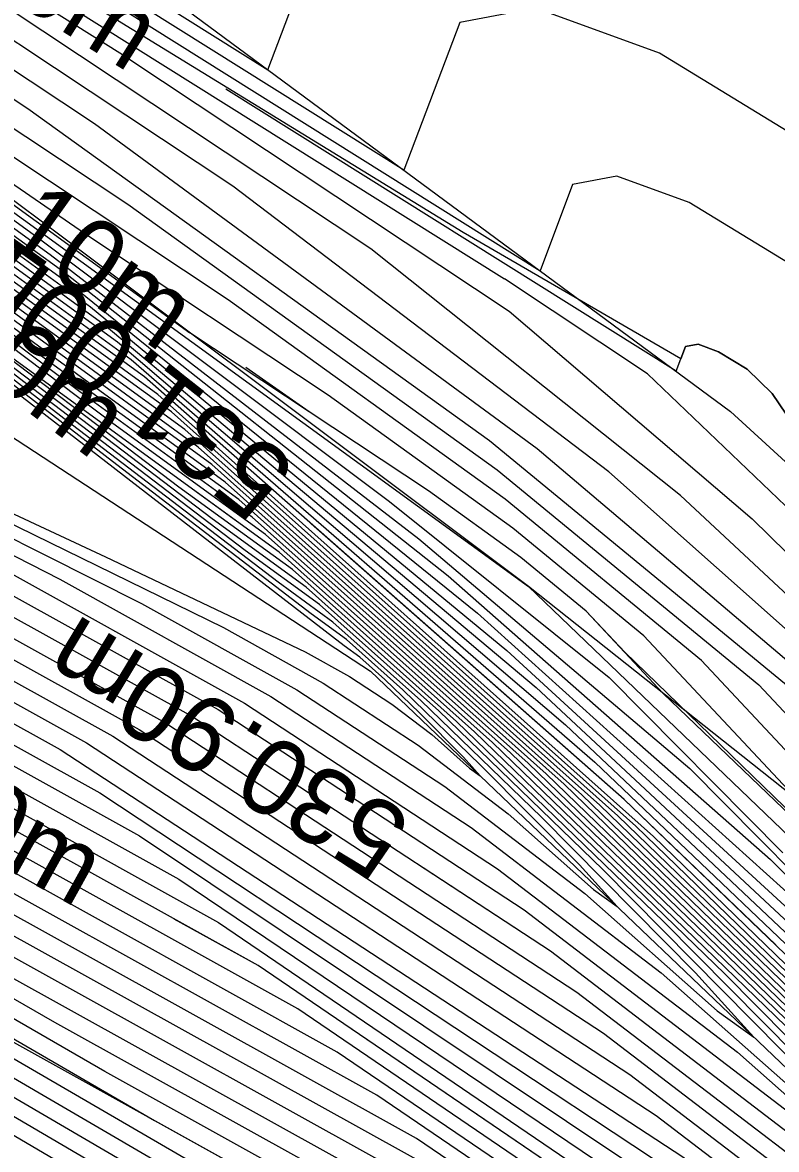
# Model space of a CAD drawing. Extents: x -866683 to -866410, y -1041951 to -1040252.
# Drawn here: x -866440.22 to -866437.24, y -1041918.091 to -1041913.64 of the extents above; entities that cross this region are included whole.
import ezdxf

# ---------------------------------------------------------------- set-up
doc = ezdxf.new("R2010")
doc.units = 0
for name, color, linetype in [('BODY', 7, 'Continuous'), ('BODY_2016', 7, 'Continuous'), ('BREAKLINE', 7, 'Continuous'), ('V-HL', 7, 'Continuous'), ('V-VEDL', 7, 'Continuous'), ('V_po_cm', 7, 'Continuous')]:
    doc.layers.add(name, color=color, linetype=linetype)

msp = doc.modelspace()

# ---------------------------------------------------------------- linework, layer by layer
at = {"layer": 'BREAKLINE'}
for points in [[(-866451.679, -1041950.508), (-866455.618, -1041922.473), (-866456.719, -1041912.396), (-866455.207, -1041909.853), (-866453.752, -1041908.342), (-866450, -1041907.538), (-866447.7, -1041908.076), (-866445.165, -1041909.459), (-866437.422, -1041915.176), (-866426.565, -1041925.108), (-866438.22, -1041915.868), (-866445.312, -1041910.554), (-866447.7, -1041908.076)], [(-866445.626, -1041911.77), (-866438.844, -1041916.202), (-866428.169, -1041926.387)]]:
    msp.add_lwpolyline(points, dxfattribs=at)
at = {"layer": 'V-HL'}
for points in [[(-866437.2433, -1041917.2832), (-866437.8418, -1041916.7086), (-866439.7378, -1041915.04), (-866442.338, -1041913.151)], [(-866436.874, -1041919.0079), (-866439.2887, -1041917.3651), (-866441.9813, -1041915.8713)]]:
    msp.add_lwpolyline(points, dxfattribs=at)
at = {"layer": 'V-VEDL'}
for points in [[(-866444.4177, -1041911.3349), (-866439.5581, -1041914.8654)], [(-866437.1745, -1041915.2278), (-866437.2577, -1041915.1049), (-866437.3558, -1041915.009), (-866437.4688, -1041914.9401), (-866437.5503, -1041914.9104), (-866437.6002, -1041914.9199), (-866437.6187, -1041914.9686), (-866438.479, -1041914.4699), (-866440.1812, -1041913.4239)], [(-866442.5339, -1041914.7256), (-866439.5509, -1041916.3805), (-866438.1333, -1041917.3074), (-866436.7895, -1041918.3338), (-866435.5196, -1041919.4596), (-866435.1652, -1041919.7133), (-866435.7263, -1041919.0949), (-866437.2029, -1041917.6045), (-866438.3627, -1041916.4834), (-866439.2058, -1041915.7317), (-866440.2582, -1041914.9671)], [(-866427.6159, -1041925.946), (-866434.3305, -1041919.5086), (-866436.6195, -1041917.3087), (-866437.8401, -1041916.1275), (-866437.9924, -1041915.9651), (-866438.251, -1041915.7527), (-866438.6158, -1041915.4903), (-866439.5581, -1041914.8654)], [(-866441.6705, -1041916.8829), (-866437.7247, -1041919.072), (-866435.6089, -1041920.5114), (-866433.3503, -1041922.2956), (-866428.5474, -1041926.5536)]]:
    msp.add_lwpolyline(points, dxfattribs=at)
at = {"layer": 'V_po_cm'}
for points in [[(-866435.0469, -1041921.2152), (-866436.9427, -1041919.9254), (-866438.7106, -1041918.9447), (-866440.4558, -1041917.9193), (-866442.1783, -1041916.8494), (-866443.8783, -1041915.7348), (-866445.0517, -1041915.0023), (-866445.6985, -1041914.6519), (-866445.8188, -1041914.6836), (-866446.0099, -1041914.5257), (-866446.2718, -1041914.1783), (-866446.6045, -1041913.6413), (-866446.7592, -1041913.2564), (-866446.7361, -1041913.0236), (-866446.5351, -1041912.9428), (-866446.5915, -1041912.6551), (-866446.9053, -1041912.1604), (-866447.4766, -1041911.4587), (-866447.7506, -1041910.8145), (-866447.7273, -1041910.2278), (-866447.4067, -1041909.6986), (-866447.002, -1041909.4933), (-866446.5131, -1041909.6119), (-866445.3672, -1041910.4968)], [(-866445.9977, -1041909.8425), (-866445.4973, -1041909.9944), (-866444.6642, -1041910.4624), (-866443.2481, -1041911.3223), (-866439.2502, -1041913.8262)], [(-866438.7125, -1041914.2232), (-866443.0739, -1041911.4917), (-866444.6015, -1041910.5588), (-866445.476, -1041910.0588), (-866445.9189, -1041909.9243)], [(-866445.84, -1041910.0061), (-866445.4547, -1041910.1231), (-866444.5388, -1041910.6553), (-866442.8996, -1041911.6611), (-866438.1748, -1041914.6202)], [(-866433.8924, -1041920.7967), (-866436.2376, -1041918.4294), (-866438.0796, -1041916.6489), (-866439.4186, -1041915.455), (-866440.2543, -1041914.8478), (-866441.2908, -1041914.0728), (-866442.5279, -1041913.1298), (-866443.9657, -1041912.019), (-866445.0628, -1041911.1714), (-866445.8192, -1041910.5872), (-866446.2349, -1041910.2662), (-866446.587, -1041910.1759), (-866446.8755, -1041910.3165), (-866447.3254, -1041911.0592), (-866445.9448, -1041912.755), (-866445.4235, -1041913.3485), (-866445.0711, -1041913.6876), (-866444.8878, -1041913.7724), (-866443.9759, -1041914.2669), (-866442.3355, -1041915.1713), (-866439.9667, -1041916.4855), (-866437.7152, -1041917.9576), (-866435.581, -1041919.5877), (-866433.5641, -1041921.3758)], [(-866445.6824, -1041910.1696), (-866445.4121, -1041910.2517), (-866444.5485, -1041910.7635), (-866442.9564, -1041911.7461), (-866438.3152, -1041914.6528)], [(-866436.4789, -1041918.2232), (-866438.1504, -1041916.6075), (-866439.3654, -1041915.5242), (-866440.1238, -1041914.9732), (-866441.1322, -1041914.2174), (-866442.3908, -1041913.2567), (-866443.8994, -1041912.0912), (-866445.0409, -1041911.2093), (-866445.8152, -1041910.6111), (-866446.2225, -1041910.2966), (-866446.5675, -1041910.2082), (-866446.8502, -1041910.3459), (-866447.291, -1041911.0736), (-866445.9384, -1041912.7351), (-866445.3652, -1041913.3454), (-866444.8953, -1041913.7353), (-866444.5285, -1041913.9048), (-866443.5675, -1041914.4152), (-866442.0123, -1041915.2667), (-866439.8628, -1041916.4592), (-866437.8197, -1041917.7951), (-866435.8831, -1041919.2742)], [(-866436.7203, -1041918.0169), (-866438.2212, -1041916.5661), (-866439.3122, -1041915.5933), (-866439.9932, -1041915.0986), (-866440.9736, -1041914.362), (-866442.2536, -1041913.3836), (-866443.833, -1041912.1633), (-866445.0189, -1041911.2471), (-866445.8113, -1041910.635), (-866446.2102, -1041910.327), (-866446.5481, -1041910.2405), (-866446.8249, -1041910.3753), (-866447.2566, -1041911.088), (-866445.9319, -1041912.7151), (-866445.307, -1041913.3422), (-866444.7194, -1041913.7829), (-866444.1693, -1041914.0371), (-866443.1591, -1041914.5636), (-866441.689, -1041915.3622), (-866439.7588, -1041916.433), (-866437.9242, -1041917.6325), (-866436.1852, -1041918.9607)], [(-866439.8039, -1041913.7807), (-866443.4576, -1041911.4925), (-866444.7109, -1041910.7189), (-866445.3908, -1041910.316), (-866445.6036, -1041910.2514)], [(-866436.9616, -1041917.8107), (-866438.292, -1041916.5247), (-866439.259, -1041915.6625), (-866439.8626, -1041915.224), (-866440.8151, -1041914.5066), (-866442.1165, -1041913.5105), (-866443.7667, -1041912.2355), (-866444.997, -1041911.285), (-866445.8074, -1041910.659), (-866446.1979, -1041910.3575), (-866446.5286, -1041910.2727), (-866446.7996, -1041910.4048), (-866447.2222, -1041911.1024), (-866445.9255, -1041912.6952), (-866445.2487, -1041913.3391), (-866444.5436, -1041913.8305), (-866443.81, -1041914.1695), (-866442.7507, -1041914.7119), (-866441.3657, -1041915.4576), (-866439.6549, -1041916.4067), (-866438.0288, -1041917.4699), (-866436.4874, -1041918.6473)], [(-866436.1848, -1041918.6695), (-866437.4443, -1041917.3982), (-866438.4335, -1041916.442), (-866439.1526, -1041915.8008), (-866439.6014, -1041915.4748), (-866440.4979, -1041914.7959), (-866441.8422, -1041913.7642), (-866443.6341, -1041912.3798), (-866444.9532, -1041911.3607), (-866445.7996, -1041910.7069), (-866446.1732, -1041910.4184), (-866446.4897, -1041910.3373), (-866446.7491, -1041910.4636), (-866447.1534, -1041911.1311), (-866445.9126, -1041912.6553), (-866445.1322, -1041913.3328), (-866444.1918, -1041913.9258), (-866443.0915, -1041914.4343), (-866441.934, -1041915.0085), (-866440.7191, -1041915.6485), (-866439.4469, -1041916.3542), (-866438.2378, -1041917.1448), (-866437.0916, -1041918.0203)], [(-866436.6433, -1041918.2441), (-866437.6856, -1041917.192), (-866438.5043, -1041916.4006), (-866439.0994, -1041915.87), (-866439.4708, -1041915.6001), (-866440.3394, -1041914.9405), (-866441.705, -1041913.8911), (-866443.5677, -1041912.452), (-866444.9313, -1041911.3985), (-866445.7957, -1041910.7308), (-866446.1609, -1041910.4488), (-866446.4703, -1041910.3696), (-866446.7238, -1041910.493), (-866447.119, -1041911.1455), (-866445.9061, -1041912.6354), (-866445.0739, -1041913.3297), (-866444.016, -1041913.9735), (-866442.7323, -1041914.5666), (-866441.5256, -1041915.1568), (-866440.3958, -1041915.7439), (-866439.343, -1041916.328), (-866438.3423, -1041916.9823), (-866437.3938, -1041917.7068), (-866436.4974, -1041918.5015)], [(-866437.1018, -1041917.8186), (-866437.9269, -1041916.9857), (-866438.5751, -1041916.3592), (-866439.0462, -1041915.9392), (-866439.3402, -1041915.7255), (-866440.1808, -1041915.0851), (-866441.5679, -1041914.018), (-866443.5014, -1041912.5242), (-866444.9094, -1041911.4364), (-866445.7918, -1041910.7548), (-866446.1486, -1041910.4793), (-866446.4508, -1041910.4018), (-866446.6985, -1041910.5225), (-866447.0846, -1041911.1599), (-866445.8997, -1041912.6154), (-866445.0156, -1041913.3266), (-866443.8401, -1041914.0211), (-866442.373, -1041914.699), (-866441.1172, -1041915.3051), (-866440.0725, -1041915.8393), (-866439.239, -1041916.3017), (-866438.4468, -1041916.8197), (-866437.6959, -1041917.3933), (-866436.9862, -1041918.0224)], [(-866444.2699, -1041911.1645), (-866439.9355, -1041914.039), (-866438.1861, -1041915.322), (-866436.8545, -1041916.4507), (-866435.0268, -1041918.3995)], [(-866434.4947, -1041918.8214), (-866436.6269, -1041916.5478), (-866437.903, -1041915.415), (-866439.3891, -1041914.2862), (-866442.7812, -1041912.0365)], [(-866442.5549, -1041912.4171), (-866440.1992, -1041913.9793), (-866438.375, -1041915.2915), (-866437.0821, -1041916.3536)], [(-866444.9574, -1041913.3234), (-866443.6642, -1041914.0687), (-866442.0138, -1041914.8314), (-866440.7088, -1041915.4534), (-866439.7492, -1041915.9348), (-866439.1351, -1041916.2755), (-866438.5513, -1041916.6572), (-866437.998, -1041917.0798), (-866437.4751, -1041917.5434), (-866437.3292, -1041917.6478), (-866437.5602, -1041917.3932), (-866438.1683, -1041916.7795), (-866438.6458, -1041916.3179), (-866438.993, -1041916.0083), (-866439.2096, -1041915.8509), (-866440.0222, -1041915.2298), (-866441.4307, -1041914.1449), (-866443.4351, -1041912.5963)], [(-866444.8991, -1041913.3203), (-866443.4884, -1041914.1164), (-866441.6546, -1041914.9638), (-866440.3004, -1041915.6017), (-866439.4259, -1041916.0302), (-866439.0311, -1041916.2492), (-866438.6559, -1041916.4946), (-866438.3002, -1041916.7663), (-866437.964, -1041917.0643), (-866437.8702, -1041917.1315), (-866438.0187, -1041916.9678), (-866438.4096, -1041916.5732), (-866438.7166, -1041916.2765), (-866438.9398, -1041916.0775), (-866439.0791, -1041915.9763), (-866439.8637, -1041915.3744), (-866441.2936, -1041914.2718), (-866443.3688, -1041912.6685)], [(-866444.8408, -1041913.3172), (-866443.3125, -1041914.164), (-866441.2953, -1041915.0962), (-866439.892, -1041915.75), (-866439.1026, -1041916.1257), (-866438.9272, -1041916.223), (-866438.7604, -1041916.332), (-866438.6023, -1041916.4528), (-866438.4529, -1041916.5852), (-866438.4112, -1041916.6151), (-866438.4772, -1041916.5423), (-866438.6509, -1041916.367), (-866438.7874, -1041916.2351), (-866438.8866, -1041916.1467), (-866438.9485, -1041916.1017), (-866439.7051, -1041915.519), (-866441.1564, -1041914.3987), (-866443.3025, -1041912.7407)], [(-866442.7179, -1041912.7711), (-866441.4296, -1041913.7193), (-866439.8974, -1041914.8325), (-866438.1897, -1041916.2673), (-866436.3065, -1041918.0236)], [(-866435.7549, -1041918.8419), (-866437.9381, -1041916.7316), (-866439.525, -1041915.3167), (-866440.5155, -1041914.597), (-866441.6079, -1041913.7835), (-866442.8022, -1041912.876)], [(-866442.5593, -1041912.9157), (-866441.299, -1041913.8447), (-866439.8442, -1041914.9017), (-866438.0737, -1041916.4144), (-866435.9876, -1041918.3828)], [(-866433.9625, -1041919.2433), (-866436.3993, -1041916.6449), (-866437.6199, -1041915.508), (-866438.8427, -1041914.5334), (-866441.2926, -1041912.9086)], [(-866439.2502, -1041913.8262), (-866438.9369, -1041912.9993), (-866438.5124, -1041912.9187), (-866437.82, -1041913.1711), (-866436.8597, -1041913.7564), (-866436.0257, -1041914.5713), (-866435.318, -1041915.6159), (-866434.7367, -1041916.8901), (-866433.9729, -1041918.1408), (-866433.0266, -1041919.3679), (-866430.7693, -1041921.7748)], [(-866442.2132, -1041912.967), (-866438.22, -1041915.868)], [(-866437.1556, -1041916.7118), (-866437.7648, -1041916.0622), (-866438.282, -1041915.6374), (-866439.0117, -1041915.1125), (-866439.954, -1041914.4876), (-866440.9965, -1041913.77), (-866442.1394, -1041912.9596)], [(-866436.6234, -1041917.1338), (-866437.5372, -1041916.1594), (-866438.313, -1041915.5221), (-866439.4075, -1041914.7348), (-866440.8209, -1041913.7974), (-866442.052, -1041912.9627)], [(-866442.4008, -1041913.0604), (-866441.1685, -1041913.9701), (-866439.791, -1041914.9708), (-866437.9577, -1041916.5615), (-866435.6687, -1041918.7421)], [(-866442.0826, -1041913.0924), (-866440.1634, -1041914.4867), (-866438.7696, -1041915.5316), (-866437.9011, -1041916.2273), (-866437.2149, -1041916.9199)], [(-866441.6879, -1041913.1072), (-866439.8034, -1041914.3571), (-866438.344, -1041915.4068), (-866437.3097, -1041916.2565), (-866436.0912, -1041917.5557)], [(-866441.952, -1041913.2178), (-866440.1102, -1041914.5558), (-866438.6536, -1041915.6788), (-866437.5822, -1041916.5865), (-866436.2098, -1041917.9718)], [(-866437.0991, -1041919.7548), (-866438.908, -1041918.7512), (-866440.6522, -1041917.7293), (-866442.3318, -1041916.6889), (-866443.9467, -1041915.6301), (-866445.0614, -1041914.9342), (-866445.6759, -1041914.6013), (-866445.7902, -1041914.6314), (-866445.9717, -1041914.4814), (-866446.2205, -1041914.1514), (-866446.5366, -1041913.6412), (-866446.6836, -1041913.2756)], [(-866435.2717, -1041920.9337), (-866437.2555, -1041919.5841), (-866439.1054, -1041918.5578), (-866440.8486, -1041917.5393), (-866442.4852, -1041916.5284), (-866444.0151, -1041915.5253), (-866445.0712, -1041914.8661), (-866445.6534, -1041914.5507), (-866445.7616, -1041914.5792), (-866445.9336, -1041914.4371), (-866446.1693, -1041914.1244), (-866446.4687, -1041913.6412), (-866446.608, -1041913.2947)], [(-866446.5324, -1041913.3139), (-866446.4008, -1041913.6411), (-866446.1181, -1041914.0975), (-866445.8955, -1041914.3929), (-866445.733, -1041914.5271), (-866445.6308, -1041914.5001), (-866445.081, -1041914.798), (-866444.0836, -1041915.4206), (-866442.6386, -1041916.368), (-866441.045, -1041917.3492), (-866439.3028, -1041918.3644), (-866437.4119, -1041919.4134), (-866435.3841, -1041920.7929)], [(-866446.4568, -1041913.3331), (-866446.333, -1041913.641), (-866446.0668, -1041914.0706), (-866445.8573, -1041914.3486), (-866445.7044, -1041914.4749), (-866445.6082, -1041914.4495), (-866445.0907, -1041914.7299), (-866444.152, -1041915.3159), (-866442.7921, -1041916.2075), (-866441.2415, -1041917.1592), (-866439.5002, -1041918.1709), (-866437.5683, -1041919.2427), (-866435.4965, -1041920.6521)], [(-866435.7214, -1041920.3706), (-866437.8811, -1041918.9013), (-866439.895, -1041917.784), (-866441.6343, -1041916.7791), (-866443.0989, -1041915.8866), (-866444.2889, -1041915.1064), (-866445.1103, -1041914.5936), (-866445.5631, -1041914.3484), (-866445.6473, -1041914.3705), (-866445.781, -1041914.26), (-866445.9643, -1041914.0168), (-866446.1972, -1041913.6409), (-866446.3056, -1041913.3715)], [(-866435.0309, -1041919.4606), (-866437.7258, -1041916.8558), (-866439.6846, -1041915.1092), (-866440.9073, -1041914.2209), (-866442.0836, -1041913.3496)], [(-866441.8214, -1041913.3432), (-866440.057, -1041914.625), (-866438.5376, -1041915.8259), (-866437.2633, -1041916.9458), (-866435.2047, -1041919.0237)], [(-866435.8338, -1041920.2298), (-866438.0375, -1041918.7306), (-866440.0925, -1041917.5906), (-866441.8307, -1041916.5891), (-866443.2524, -1041915.7261), (-866444.3573, -1041915.0016), (-866445.12, -1041914.5255), (-866445.5405, -1041914.2978), (-866445.6187, -1041914.3183), (-866445.7429, -1041914.2157), (-866445.9131, -1041913.9899), (-866446.1294, -1041913.6408), (-866446.23, -1041913.3906)], [(-866435.9462, -1041920.0891), (-866438.1939, -1041918.56), (-866440.2899, -1041917.3972), (-866442.0272, -1041916.399), (-866443.4058, -1041915.5656), (-866444.4258, -1041914.8969), (-866445.1298, -1041914.4574), (-866445.5179, -1041914.2472), (-866445.5901, -1041914.2662), (-866445.7047, -1041914.1714), (-866445.8619, -1041913.963), (-866446.0615, -1041913.6408), (-866446.1543, -1041913.4098)], [(-866436.0586, -1041919.9483), (-866438.3503, -1041918.3893), (-866440.4873, -1041917.2037), (-866442.2236, -1041916.209), (-866443.5592, -1041915.4052), (-866444.4942, -1041914.7922), (-866445.1396, -1041914.3893), (-866445.4953, -1041914.1966), (-866445.5615, -1041914.214), (-866445.6666, -1041914.1271), (-866445.8106, -1041913.9361), (-866445.9936, -1041913.6407), (-866446.0787, -1041913.429)], [(-866436.171, -1041919.8076), (-866438.5067, -1041918.2186), (-866440.6847, -1041917.0103), (-866442.42, -1041916.019), (-866443.7127, -1041915.2447), (-866444.5626, -1041914.6874), (-866445.1493, -1041914.3212), (-866445.4728, -1041914.146), (-866445.5329, -1041914.1618), (-866445.6284, -1041914.0829), (-866445.7594, -1041913.9091), (-866445.9257, -1041913.6406), (-866446.0031, -1041913.4482)], [(-866436.2834, -1041919.6668), (-866438.6631, -1041918.0479), (-866440.8821, -1041916.8168), (-866442.6164, -1041915.8289), (-866443.8661, -1041915.0842), (-866444.6311, -1041914.5827), (-866445.1591, -1041914.2531), (-866445.4502, -1041914.0954), (-866445.5043, -1041914.1096), (-866445.5903, -1041914.0386), (-866445.7082, -1041913.8822), (-866445.8579, -1041913.6406), (-866445.9275, -1041913.4674)], [(-866441.6908, -1041913.4686), (-866440.0038, -1041914.6942), (-866438.4216, -1041915.973), (-866436.9444, -1041917.3051)], [(-866436.3958, -1041919.526), (-866438.8195, -1041917.8772), (-866441.0795, -1041916.6234), (-866442.8129, -1041915.6389), (-866444.0195, -1041914.9237), (-866444.6995, -1041914.4779), (-866445.1689, -1041914.1849), (-866445.4276, -1041914.0448), (-866445.4757, -1041914.0574), (-866445.5522, -1041913.9943), (-866445.6569, -1041913.8553), (-866445.79, -1041913.6405), (-866445.8519, -1041913.4865)], [(-866436.5082, -1041919.3853), (-866438.9759, -1041917.7065), (-866441.2769, -1041916.4299), (-866443.0093, -1041915.4489), (-866444.173, -1041914.7633), (-866444.7679, -1041914.3732), (-866445.1786, -1041914.1168), (-866445.405, -1041913.9942), (-866445.4471, -1041914.0053), (-866445.514, -1041913.95), (-866445.6057, -1041913.8284), (-866445.7221, -1041913.6404), (-866445.7763, -1041913.5057)], [(-866435.2722, -1041919.2544), (-866437.7966, -1041916.8144), (-866439.6314, -1041915.1783), (-866440.7767, -1041914.3463), (-866441.9251, -1041913.4942)], [(-866436.6206, -1041919.2445), (-866439.1323, -1041917.5358), (-866441.4744, -1041916.2365), (-866443.2057, -1041915.2588), (-866444.3264, -1041914.6028), (-866444.8364, -1041914.2684), (-866445.1884, -1041914.0487), (-866445.3825, -1041913.9436), (-866445.4185, -1041913.9531), (-866445.4759, -1041913.9057), (-866445.5544, -1041913.8015), (-866445.6542, -1041913.6404), (-866445.7007, -1041913.5249)], [(-866445.5494, -1041913.5633), (-866445.5185, -1041913.6403), (-866445.452, -1041913.7477), (-866445.3996, -1041913.8171), (-866445.3614, -1041913.8487), (-866445.3132, -1041913.8361), (-866444.6333, -1041914.2819), (-866443.5986, -1041914.8788), (-866441.8692, -1041915.8496), (-866439.4451, -1041917.1945), (-866436.8455, -1041918.963)], [(-866445.4738, -1041913.5825), (-866445.4506, -1041913.6402), (-866445.4007, -1041913.7207), (-866445.3614, -1041913.7729), (-866445.3328, -1041913.7965), (-866445.2967, -1041913.787), (-866444.7867, -1041914.1214), (-866443.795, -1041914.6887), (-866442.0666, -1041915.6562), (-866439.6015, -1041917.0238), (-866437.0368, -1041918.7523)], [(-866445.3982, -1041913.6016), (-866445.3827, -1041913.6401), (-866445.3495, -1041913.6938), (-866445.3233, -1041913.7286), (-866445.3042, -1041913.7444), (-866445.2801, -1041913.738), (-866444.9401, -1041913.9609), (-866443.9914, -1041914.4987), (-866442.264, -1041915.4627), (-866439.7579, -1041916.8531), (-866437.2281, -1041918.5416)], [(-866441.5602, -1041913.5939), (-866439.9506, -1041914.7633), (-866438.3057, -1041916.1201), (-866436.6255, -1041917.6643)], [(-866431.3015, -1041921.3529), (-866433.8446, -1041918.6413), (-866434.829, -1041917.4376), (-866435.5265, -1041916.386), (-866435.9369, -1041915.4865), (-866436.4364, -1041914.7491), (-866437.0251, -1041914.1739), (-866437.703, -1041913.7608), (-866438.1917, -1041913.5826), (-866438.4914, -1041913.6395), (-866438.7125, -1041914.2232)], [(-866445.3226, -1041913.6208), (-866445.3149, -1041913.6401), (-866445.2982, -1041913.6669), (-866445.2851, -1041913.6843), (-866445.2756, -1041913.6922), (-866445.2636, -1041913.689), (-866445.0936, -1041913.8005), (-866444.1879, -1041914.3087), (-866442.4614, -1041915.2693), (-866439.9143, -1041916.6824), (-866437.4194, -1041918.3309), (-866434.9767, -1041920.2147)], [(-866435.5136, -1041919.0482), (-866437.8673, -1041916.773), (-866439.5782, -1041915.2475), (-866440.6461, -1041914.4717), (-866441.7665, -1041913.6389)], [(-866439.8039, -1041913.7807), (-866438.2963, -1041914.7805), (-866437.3368, -1041915.601), (-866436.1717, -1041916.7421), (-866433.4303, -1041919.6653)], [(-866437.6371, -1041915.0172), (-866439.4169, -1041913.9026)], [(-866431.8337, -1041920.931), (-866434.6625, -1041917.9147), (-866435.6852, -1041916.7343), (-866436.3163, -1041915.8818), (-866436.5557, -1041915.3571), (-866436.8471, -1041914.927), (-866437.1905, -1041914.5914), (-866437.5859, -1041914.3504), (-866437.871, -1041914.2465), (-866438.0458, -1041914.2797), (-866438.1748, -1041914.6202)], [(-866432.8981, -1041920.0872), (-866435.9441, -1041916.8392), (-866437.0537, -1041915.694), (-866437.7498, -1041915.0277), (-866438.3152, -1041914.6528)], [(-866437.6371, -1041915.0172), (-866437.6002, -1041914.9199), (-866437.5503, -1041914.9104), (-866437.4688, -1041914.9401), (-866437.3558, -1041915.009), (-866437.2577, -1041915.1049), (-866437.1745, -1041915.2278), (-866437.1061, -1041915.3777), (-866436.5414, -1041916.0311), (-866436.2629, -1041916.3348)], [(-866437.6878, -1041916.2899), (-866437.9924, -1041915.9651), (-866438.251, -1041915.7527), (-866438.6158, -1041915.4903), (-866439.087, -1041915.1778), (-866439.3367, -1041915.0022)], [(-866436.8092, -1041918.0019), (-866437.2029, -1041917.6045), (-866438.3627, -1041916.4834), (-866439.2058, -1041915.7317), (-866439.5279, -1041915.4976)], [(-866436.0016, -1041918.4755), (-866437.8418, -1041916.7086), (-866439.0786, -1041915.6201)], [(-866427.6662, -1041925.9861), (-866438.22, -1041915.868)], [(-866437.6878, -1041916.2899), (-866436.1719, -1041917.7432)], [(-866438.6368, -1041916.9782), (-866438.1333, -1041917.3074), (-866436.7895, -1041918.3338), (-866436.7599, -1041918.36)], [(-866436.1604, -1041919.5561), (-866436.7331, -1041919.1038), (-866439.2887, -1041917.3651), (-866439.6203, -1041917.1812)], [(-866440.65, -1041917.4257), (-866439.6976, -1041917.9775), (-866437.7247, -1041919.072), (-866437.0279, -1041919.546)]]:
    msp.add_lwpolyline(points, dxfattribs=at)
msp.add_lwpolyline([(-866447.3599, -1041911.0448), (-866445.9513, -1041912.7749), (-866444.619, -1041913.8303), (-866442.6588, -1041915.0759), (-866440.0707, -1041916.5117), (-866437.6107, -1041918.1202), (-866435.2789, -1041919.9012), (-866433.0752, -1041921.8549), (-866432.4602, -1041922.2952), (-866433.4339, -1041921.2221), (-866435.9962, -1041918.6357), (-866438.0089, -1041916.6902), (-866439.4718, -1041915.3858), (-866440.3849, -1041914.7224), (-866441.4494, -1041913.9281), (-866442.665, -1041913.0029), (-866444.032, -1041911.9468), (-866445.0847, -1041911.1336), (-866445.8231, -1041910.5632), (-866446.2472, -1041910.2357), (-866446.6064, -1041910.1437), (-866446.9008, -1041910.2871)], close=True, dxfattribs=at)

# ---------------------------------------------------------------- texts
at = {"layer": 'BODY'}
for p in [(-866437.422, -1041915.176), (-866438.22, -1041915.868), (-866438.844, -1041916.202)]:
    msp.add_text('+', height=0.001, rotation=360, dxfattribs=at).set_placement(p)
at = {"layer": 'BODY_2016'}
for p in [(-866437.422, -1041915.176), (-866438.22, -1041915.868), (-866438.844, -1041916.202)]:
    msp.add_text('+', height=0.001, rotation=360, dxfattribs=at).set_placement(p)
at = {"layer": 'V_po_cm'}
for s, rotation, p in [('531.20m', 327.9418, (-866441.1228, -1041913.0111)), ('531.10m', 324.5086, (-866440.9447, -1041914.0398)), ('530.90m', 322.935, (-866441.1903, -1041914.4299)), ('531.00m', 141.7672, (-866439.1279, -1041915.3902)), ('530.90m', 148.8183, (-866438.6703, -1041916.7825)), ('531.00m', 330.9794, (-866441.3711, -1041916.3814))]:
    msp.add_text(s, height=0.3, rotation=rotation, dxfattribs=at).set_placement(p)

doc.saveas('drawing.dxf')
